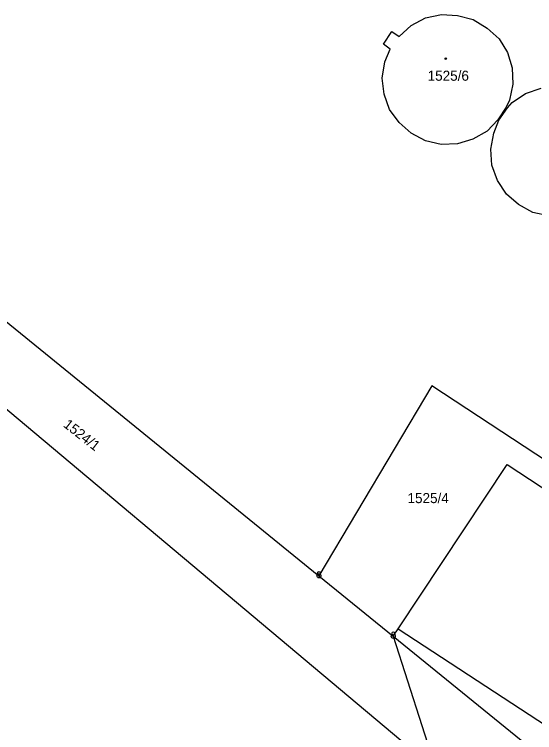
# Model space of a CAD drawing. Extents: x -593051 to -592421, y -1177053 to -1176567.
# Drawn here: x -592910.4 to -592846, y -1176971.5 to -1176882.5 of the extents above; entities that cross this region are included whole.
import ezdxf

# ---------------------------------------------------------------- set-up
doc = ezdxf.new("R2010")
doc.units = 0
doc.layers.add('DKM', color=7, linetype='Continuous')

msp = doc.modelspace()

# ---------------------------------------------------------------- linework, layer by layer
at = {"layer": 'DKM'}
for points in [[(-592859.45, -1176882.97), (-592857.5, -1176882.52)], [(-592857.5, -1176882.52), (-592855.51, -1176882.64)], [(-592855.51, -1176882.64), (-592853.56, -1176883.15)], [(-592861.22, -1176883.9), (-592859.45, -1176882.97)], [(-592853.56, -1176883.15), (-592851.83, -1176884.21)], [(-592864.66, -1176886.23), (-592863.64, -1176884.66)], [(-592863.64, -1176884.66), (-592862.73, -1176885.27)], [(-592862.73, -1176885.27), (-592861.22, -1176883.9)], [(-592851.83, -1176884.21), (-592850.35, -1176885.56)], [(-592850.35, -1176885.56), (-592849.31, -1176887.25)], [(-592863.83, -1176886.83), (-592864.66, -1176886.23)], [(-592864.51, -1176888.4), (-592863.83, -1176886.83)], [(-592849.31, -1176887.25), (-592848.73, -1176889.16)], [(-592864.82, -1176890.41), (-592864.51, -1176888.4)], [(-592848.73, -1176889.16), (-592848.66, -1176891.17)], [(-592864.58, -1176892.4), (-592864.82, -1176890.41)], [(-592848.66, -1176891.17), (-592849.06, -1176893.16)], [(-592847.06, -1176892.34), (-592845.14, -1176891.68)], [(-592863.91, -1176894.31), (-592864.58, -1176892.4)], [(-592848.74, -1176893.45), (-592847.06, -1176892.34)], [(-592849.06, -1176893.16), (-592849.47, -1176894.02)], [(-592849.29, -1176894.11), (-592848.74, -1176893.45)], [(-592862.74, -1176895.93), (-592863.91, -1176894.31)], [(-592849.47, -1176894.02), (-592850.51, -1176895.59)], [(-592850.38, -1176895.65), (-592849.29, -1176894.11)], [(-592861.22, -1176897.24), (-592862.74, -1176895.93)], [(-592850.51, -1176895.59), (-592851.82, -1176897.01)], [(-592851.02, -1176897.25), (-592850.38, -1176895.65)], [(-592851.82, -1176897.01), (-592853.59, -1176897.98)], [(-592859.48, -1176898.18), (-592861.22, -1176897.24)], [(-592853.59, -1176897.98), (-592855.49, -1176898.58)], [(-592851.38, -1176899.23), (-592851.02, -1176897.25)], [(-592857.52, -1176898.63), (-592859.48, -1176898.18)], [(-592855.49, -1176898.58), (-592857.52, -1176898.63)], [(-592851.23, -1176901.21), (-592851.38, -1176899.23)], [(-592850.54, -1176903.12), (-592851.23, -1176901.21)], [(-592849.44, -1176904.8), (-592850.54, -1176903.12)], [(-592847.96, -1176906.1), (-592849.44, -1176904.8)], [(-592846.17, -1176907.06), (-592847.96, -1176906.1)], [(-592927.58, -1176907.43), (-592872.66, -1176952.11)], [(-592844.22, -1176907.49), (-592846.17, -1176907.06)], [(-592858.15, -1176976.18), (-592932.63, -1176913.64)], [(-592821.35, -1176953.11), (-592858.69, -1176928.55), (-592872.66, -1176952.11)], [(-592862.83, -1176958.67), (-592849.33, -1176938.3)], [(-592849.33, -1176938.3), (-592823.03, -1176955.62)], [(-592872.66, -1176952.11), (-592863.45, -1176959.6)], [(-592863.45, -1176959.6), (-592862.83, -1176958.67)], [(-592862.83, -1176958.67), (-592812.05, -1176991.92)], [(-592863.45, -1176959.6), (-592816.14, -1176998.09)], [(-592863.45, -1176959.6), (-592858.15, -1176976.18)]]:
    msp.add_lwpolyline(points, dxfattribs=at)
for centre, radius in [((-592856.959, -1176888.01), 0.0875), ((-592872.66, -1176952.11), 0.25), ((-592872.66, -1176952.11), 0.011), ((-592863.45, -1176959.6), 0.25), ((-592863.45, -1176959.6), 0.011)]:
    msp.add_circle(centre, radius, dxfattribs=at)
for centre in [(-592872.66, -1176951.828), (-592863.45, -1176959.318)]:
    msp.add_arc(centre, 0.218, 328.48973, 209.97456, dxfattribs=at)

# ---------------------------------------------------------------- texts
for s, p in [('1525/6', (-592859.199, -1176890.75)), ('1525/4', (-592861.689, -1176943.1))]:
    msp.add_text(s, height=1.25, dxfattribs=at).set_placement(p)
msp.add_text('1524/1', height=1.25, rotation=321.90256, dxfattribs=at).set_placement((-592904.414, -1176933.555))

doc.saveas('drawing.dxf')
